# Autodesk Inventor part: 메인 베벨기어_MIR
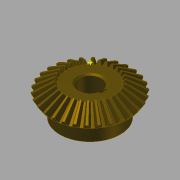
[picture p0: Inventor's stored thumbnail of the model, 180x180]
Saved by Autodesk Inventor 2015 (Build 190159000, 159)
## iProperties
Created: 2014-10
Part Number: 메인 베벨기어_MIR
Material: 강철, 탄소
Document SubType Name: Modeling
Designer: User
Categories: <?xml version="1.0" encoding="UTF-16"?> <MemberInstance><Categories><FamilyTemplate><FamilyTemplateParameter ValueType="xs:double" Id="1" ObjectReferenceKey="da
Mass: 269.926 g
Surface Area: 108.837 cm^2
Volume: 34.2981 cm^3
Density: 7.87 g/cm^3
Appearance: 반광택
Author: SeoGD™ [www.esajin.kr]
Revision Number: 1
d48: 0.000 mm
d49: 0.000 mm
d50: 90.00 deg
d52: 0.000 mm
d53: 0.000 mm
d54: 0.00 deg
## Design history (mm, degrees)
node "메인 베벨 기어"
  sketch "톱니 본체 스케치"
    geometry: L1 (0, -20)-(-31.109, -20) reference; L2 (0, 0)-(-28.669, -21.997) reference; L3 (-28.669, -21.997)-(-31.109, -18.336) reference; L4 (-31.109, -18.336)-(0, 0) reference; L5 (-30, -20)-(0, 0) reference; L6 (-17.219, -13.212)-(-18.685, -11.013) reference; L7 (-28.669, -21.997)-(-17.219, -13.212) reference; L8 (-31.109, -18.336)-(-18.685, -11.013) reference; L9 (0, -39.387)-(0, 6.564) reference
  sketch "시작 스케치"
    geometry: L1 (0, -23.505)-(0, 10.645) reference; L2 (0.709, -2.928)-(-0.709, -2.928) reference; A1 r 57.403 centre (0, -54.083) between (3.232, 3.229) and (-3.232, 3.229) reference; A2 r 19.188 centre (19.457, -7.014) between (3.232, 3.229) and (0.709, -2.928) reference; A3 r 19.188 centre (-19.457, -7.014) between (-0.709, -2.928) and (-3.232, 3.229) reference; 1 further point
  sketch "끝 스케치"
    geometry: L1 (0, -15.359)-(0, 6.983) reference; L2 (0.422, -1.69)-(-0.422, -1.69) reference; A1 r 34.184 centre (0, -32.153) between (1.925, 1.977) and (-1.925, 1.977) reference; A2 r 11.427 centre (11.587, -4.123) between (1.925, 1.977) and (0.422, -1.69) reference; A3 r 11.427 centre (-11.587, -4.123) between (-0.422, -1.69) and (-1.925, 1.977) reference; 1 further point
  sketch "끝 스케치 오른쪽"
    geometry: L1 (0, -41.54)-(0, 13.178) reference; L2 (0.422, -1.69)-(-0.422, -1.69) reference; A1 r 11.427 centre (11.587, -4.123) between (1.925, 1.977) and (0.422, -1.69) reference; A2 r 11.427 centre (-11.587, -4.123) between (-0.422, -1.69) and (-1.925, 1.977) reference; A3 r 34.184 centre (0, -32.153) between (1.925, 1.977) and (-1.925, 1.977) reference; 1 further point
  sketch "끝 스케치 왼쪽"
    geometry: L1 (0, -43.753)-(0, 15.405) reference; L2 (0.422, -1.678)-(-0.422, -1.678) reference; A1 r 34.184 centre (0, -32.142) between (1.925, 1.988) and (-1.925, 1.988) reference; A2 r 11.427 centre (11.587, -4.111) between (1.925, 1.988) and (0.422, -1.678) reference; A3 r 11.427 centre (-11.587, -4.111) between (-0.422, -1.678) and (-1.925, 1.988) reference; 2 further points; 1 other entity
    constraints: 1 other
  sketch "본체 스케치"
    geometry: L1 (0, -35.038)-(0, -19.531) reference; L2 (-28.669, -21.997)-(-17.219, -13.212) reference; L3 (-17.219, -13.212)-(0, -13.212) reference; L4 (-28.669, -21.997)-(0, -21.997) reference
  sketch "Sketch6"
    geometry: L1 (-30, -20)-(0, 0) reference; L2 (0, -37.8)-(0, 6.3) reference
  sketch "스케치8"
    geometry: C1 r 22.5 at (0, 0) reference; 1 further point
  sketch "스케치9"
    geometry: 1 further point
  sketch "스케치10"
    geometry: L1 (-10.8, -2.5)-(-8.124, -2.5) reference; L2 (-8.124, 2.5)-(-10.8, 2.5) reference; L3 (-10.8, 2.5)-(-10.8, -2.5) reference; A1 r 8.5 centre (0, 0) between (-8.124, 2.5) and (-8.124, -2.5) reference; 1 further point
  sketch "3D 스케치 오른쪽"
  sketch "3D 스케치 왼쪽"
  node "메쉬 평면"
  node "맨 위 평면"
  node "톱니 평면"
  node "끝 평면"
  node "끝 평면 왼쪽"
  node "메쉬 평면2"
  node "끝 평면 오른쪽"
  node "Z Axis_1"
  node "맨 위 점"
  node "시작점"
  node "끝점"
feature "Solid1::메인 베벨 기어"
tag "피쳐 태그1"
node "곡면1"
node "솔리드1"
feature "Srf1::파생"
other parameters: "d48" = 0, "d49" = 0, "d50" = 90 deg, "d52" = 0, "d53" = 0, "d54" = 0 deg
